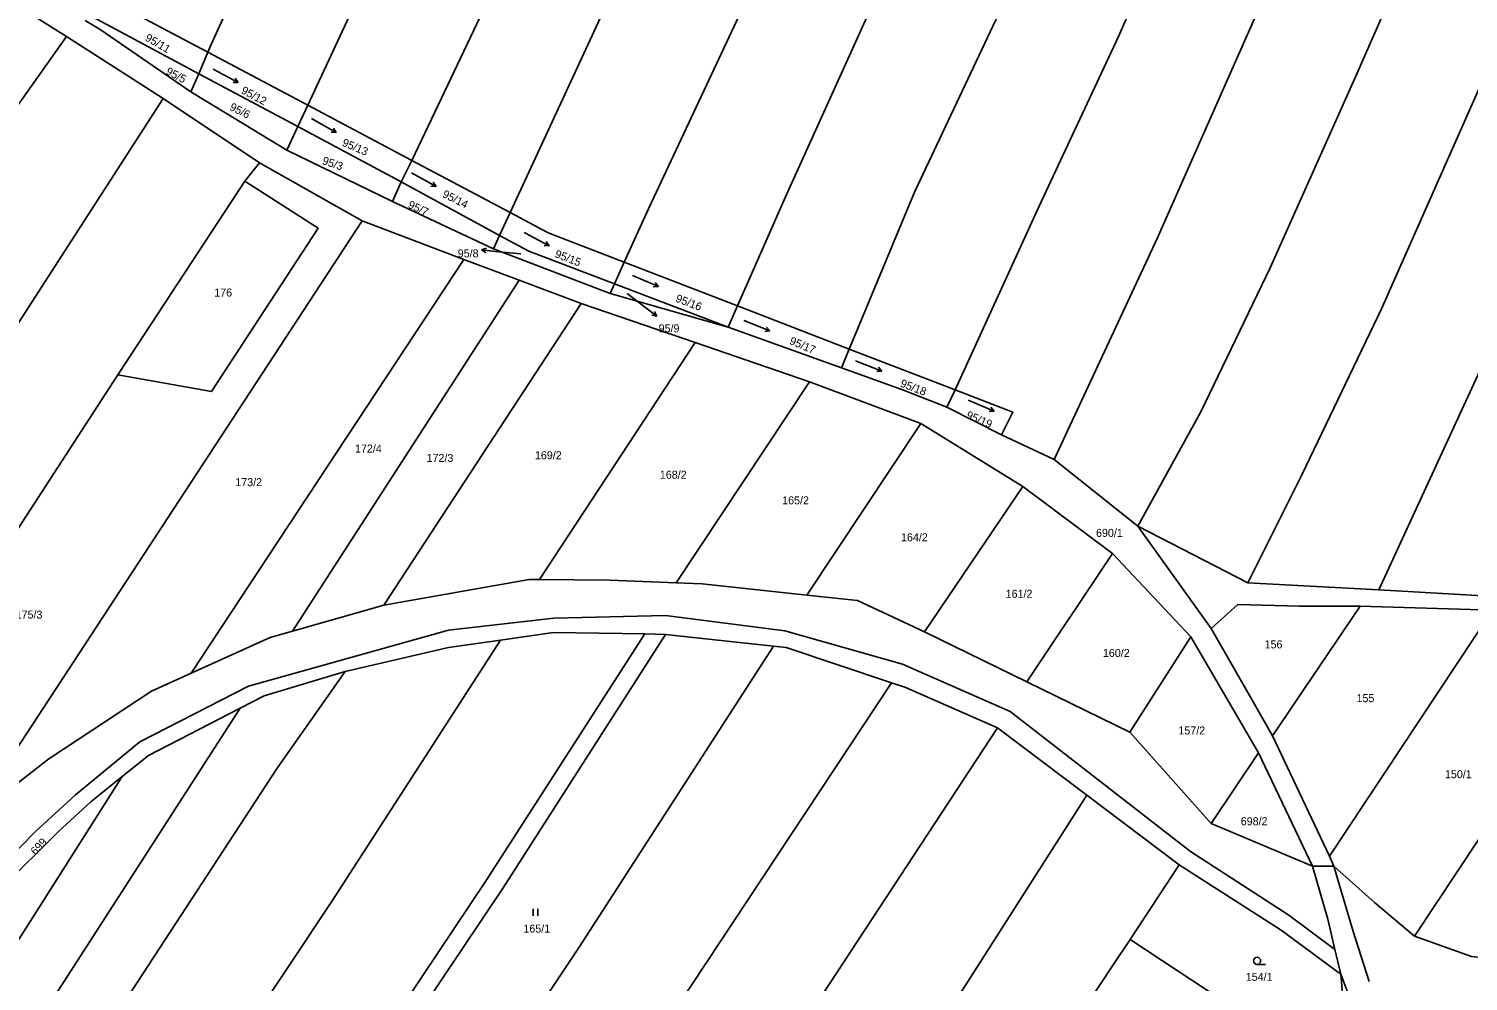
# Model space of a CAD drawing. Extents: x -747333 to -743907, y -1134120 to -1130051.
# Drawn here: x -746642.5 to -746336.6, y -1131625.6 to -1131423.1 of the extents above; entities that cross this region are included whole.
import ezdxf

# ---------------------------------------------------------------- set-up
doc = ezdxf.new("R2010")
doc.units = 0
for name, color, linetype in [('Hranice parcel', 7, 'Continuous'), ('Parcelní čísla', 7, 'Continuous'), ('Pop  PČ popisy', 7, 'Continuous'), ('Značky kultur', 7, 'Continuous')]:
    doc.layers.add(name, color=color, linetype=linetype)

msp = doc.modelspace()

# ---------------------------------------------------------------- linework, layer by layer
at = {"layer": 'Hranice parcel'}
for p, q in [((-746634.47, -1131424.8), (-746656.6, -1131410.85)), ((-746604.44, -1131428.12), (-746628.09, -1131415.58)), ((-746606.35, -1131432.7), (-746629.9, -1131420.11)), ((-746613.96, -1131437.96), (-746634.47, -1131424.8)), ((-746606.35, -1131432.7), (-746604.44, -1131428.12)), ((-746583.2, -1131439.38), (-746604.44, -1131428.12)), ((-746608.05, -1131436.52), (-746606.35, -1131432.7)), ((-746585.32, -1131443.94), (-746606.35, -1131432.7)), ((-746593.49, -1131451.66), (-746613.96, -1131437.96)), ((-746608.05, -1131436.52), (-746587.65, -1131448.97)), ((-746585.32, -1131443.94), (-746583.2, -1131439.38)), ((-746561.09, -1131451.11), (-746583.2, -1131439.38)), ((-746585.32, -1131443.94), (-746587.65, -1131448.97)), ((-746563.37, -1131455.67), (-746585.32, -1131443.94)), ((-746587.65, -1131448.97), (-746565.25, -1131459.83)), ((-746593.49, -1131451.66), (-746596.57, -1131455.55)), ((-746571.68, -1131464), (-746593.49, -1131451.66)), ((-746563.37, -1131455.67), (-746561.09, -1131451.11)), ((-746540.23, -1131462.22), (-746561.09, -1131451.11)), ((-746596.57, -1131455.55), (-746623.57, -1131496.7)), ((-746565.25, -1131459.83), (-746563.37, -1131455.67)), ((-746542.47, -1131467.06), (-746563.37, -1131455.67)), ((-746565.25, -1131459.83), (-746543.78, -1131469.9)), ((-746542.47, -1131467.06), (-746540.23, -1131462.22)), ((-746571.68, -1131464), (-746656.95, -1131594.27)), ((-746550.07, -1131472.15), (-746571.68, -1131464)), ((-746543.78, -1131469.9), (-746542.47, -1131467.06)), ((-746550.07, -1131472.15), (-746607.99, -1131560.1)), ((-746538.33, -1131476.58), (-746550.07, -1131472.15)), ((-746543.78, -1131469.9), (-746518.97, -1131479.42)), ((-746518.04, -1131477.36), (-746515.96, -1131472.78)), ((-746491.92, -1131482.06), (-746515.96, -1131472.78)), ((-746538.33, -1131476.58), (-746586.48, -1131551.19)), ((-746525.15, -1131481.55), (-746538.33, -1131476.58)), ((-746518.97, -1131479.42), (-746518.04, -1131477.36)), ((-746493.89, -1131486.54), (-746518.04, -1131477.36)), ((-746518.97, -1131479.42), (-746493.89, -1131486.54)), ((-746525.15, -1131481.55), (-746567.04, -1131545.66)), ((-746500.92, -1131489.85), (-746525.15, -1131481.55)), ((-746493.89, -1131486.54), (-746491.92, -1131482.06)), ((-746468.18, -1131491.22), (-746491.92, -1131482.06)), ((-746493.89, -1131486.54), (-746469.83, -1131495.19)), ((-746500.92, -1131489.85), (-746533.99, -1131540.23)), ((-746476.59, -1131498.19), (-746500.92, -1131489.85)), ((-746469.83, -1131495.19), (-746468.18, -1131491.22)), ((-746445.67, -1131499.91), (-746468.18, -1131491.22)), ((-746476.59, -1131498.19), (-746504.91, -1131540.89)), ((-746452.98, -1131507.05), (-746476.59, -1131498.19)), ((-746447.42, -1131503.6), (-746445.67, -1131499.91)), ((-746447.42, -1131503.6), (-746435.81, -1131509.47)), ((-746452.98, -1131507.05), (-746477.2, -1131543.56)), ((-746431.27, -1131520.46), (-746452.98, -1131507.05)), ((-746435.81, -1131509.47), (-746424.65, -1131514.71)), ((-746424.65, -1131514.71), (-746406.87, -1131528.87)), ((-746431.27, -1131520.46), (-746452.15, -1131551.35)), ((-746412.23, -1131534.7), (-746431.27, -1131520.46)), ((-746391.27, -1131550.61), (-746406.87, -1131528.87)), ((-746406.87, -1131528.87), (-746383.44, -1131540.92)), ((-746412.23, -1131534.7), (-746430.43, -1131561.92)), ((-746395.6, -1131552.41), (-746412.23, -1131534.7)), ((-746383.44, -1131540.92), (-746355.61, -1131542.43)), ((-746355.61, -1131542.43), (-746328.65, -1131543.97)), ((-746586.48, -1131551.19), (-746567.04, -1131545.66)), ((-746359.57, -1131545.85), (-746378.21, -1131573.45)), ((-746331.46, -1131546.72), (-746366.12, -1131598.98)), ((-746331.46, -1131546.72), (-746359.57, -1131545.85)), ((-746452.15, -1131551.35), (-746430.43, -1131561.92)), ((-746507.22, -1131551.86), (-746511.63, -1131551.78)), ((-746507.22, -1131551.86), (-746484.27, -1131554.35)), ((-746395.6, -1131552.41), (-746408.57, -1131572.64)), ((-746381.23, -1131577.03), (-746395.6, -1131552.41)), ((-746348.04, -1131615.98), (-746306.49, -1131553.28)), ((-746430.43, -1131561.92), (-746408.57, -1131572.64)), ((-746436.69, -1131571.7), (-746417.71, -1131586.04)), ((-746408.57, -1131572.64), (-746391.24, -1131592.08)), ((-746378.21, -1131573.45), (-746366.12, -1131598.98)), ((-746391.24, -1131592.08), (-746381.23, -1131577.03)), ((-746381.23, -1131577.03), (-746369.7, -1131601.11)), ((-746417.71, -1131586.04), (-746398.08, -1131600.88)), ((-746369.7, -1131601.11), (-746391.24, -1131592.08)), ((-746366.12, -1131598.98), (-746365.22, -1131601.11)), ((-746408.5, -1131616.68), (-746398.08, -1131600.88)), ((-746369.7, -1131601.11), (-746365.22, -1131601.11)), ((-746363.69, -1131624.1), (-746364.99, -1131618.82))]:
    msp.add_line(p, q, dxfattribs=at)
for points in [[(-746604.44, -1131428.12), (-746603.76, -1131426.5), (-746586.35, -1131388.11), (-746557.1, -1131325.3), (-746520.06, -1131246.03), (-746509.39, -1131224.25)], [(-746583.2, -1131439.38), (-746565.74, -1131401.78), (-746554.47, -1131378.66), (-746534.21, -1131333.41), (-746485.62, -1131231.14)], [(-746561.09, -1131451.11), (-746539.63, -1131405.92), (-746521.08, -1131363.53), (-746500.25, -1131318.99), (-746484.41, -1131286.87), (-746462.73, -1131237.74)], [(-746540.23, -1131462.22), (-746501.81, -1131379.22), (-746456.29, -1131281.73), (-746440.44, -1131244.89)], [(-746515.96, -1131472.78), (-746510.81, -1131461.44), (-746475.56, -1131386.07), (-746446.52, -1131320.69), (-746416.1, -1131252.46)], [(-746491.92, -1131482.06), (-746481.7, -1131458.87), (-746450.45, -1131389.79), (-746407.71, -1131295.56), (-746391.9, -1131259.94)], [(-746468.18, -1131491.22), (-746454.3, -1131457.87), (-746427.47, -1131400.92), (-746377.88, -1131289.13), (-746368.48, -1131267.37)], [(-746445.67, -1131499.91), (-746427.9, -1131461.01), (-746410.92, -1131424.76), (-746393.65, -1131385.36), (-746360.75, -1131310.12), (-746345.03, -1131274.96)], [(-746424.65, -1131514.71), (-746402.7, -1131467.7), (-746372.16, -1131398.47), (-746333.78, -1131310.4), (-746320.41, -1131282.95)], [(-746406.87, -1131528.87), (-746393.43, -1131504.53), (-746378.73, -1131473.98), (-746360.32, -1131432.73), (-746327.22, -1131357.37), (-746296.56, -1131290.28)], [(-746383.44, -1131540.92), (-746372.02, -1131517.94), (-746355.04, -1131482.69), (-746333.35, -1131433.58), (-746288.12, -1131328.39), (-746273.9, -1131297.53)], [(-746355.61, -1131542.43), (-746324.93, -1131475.84), (-746303.11, -1131426.75), (-746270.15, -1131349.38), (-746250.49, -1131305.53)], [(-746630.51, -1131421.39), (-746627.36, -1131423.33), (-746608.05, -1131436.52)], [(-746634.47, -1131424.8), (-746647.15, -1131442.71), (-746707, -1131534.29), (-746764.83, -1131622.3), (-746823.85, -1131714.89)], [(-746784.84, -1131701.9), (-746725.12, -1131609.01), (-746691.43, -1131558.02), (-746613.96, -1131437.96)], [(-746596.57, -1131455.55), (-746581, -1131465.55), (-746603.71, -1131500.27), (-746623.57, -1131496.7)], [(-746515.96, -1131472.78), (-746532.12, -1131466.54), (-746540.23, -1131462.22)], [(-746518.04, -1131477.36), (-746536.28, -1131470.43), (-746542.47, -1131467.06)], [(-746469.83, -1131495.19), (-746456.6, -1131499.95), (-746447.42, -1131503.6)], [(-746623.57, -1131496.7), (-746686.57, -1131593.72), (-746741.92, -1131680.58)], [(-746435.81, -1131509.47), (-746433.39, -1131504.65), (-746445.67, -1131499.91)], [(-746567.04, -1131545.66), (-746536.15, -1131540.21), (-746533.99, -1131540.23)], [(-746533.99, -1131540.23), (-746519.08, -1131540.36), (-746504.91, -1131540.89)], [(-746504.91, -1131540.89), (-746499.43, -1131541.1), (-746477.2, -1131543.56)], [(-746477.2, -1131543.56), (-746466.43, -1131544.63), (-746452.15, -1131551.35)], [(-746359.57, -1131545.85), (-746372.46, -1131545.89), (-746385.61, -1131545.48), (-746391.27, -1131550.61)], [(-746364.99, -1131618.82), (-746374.76, -1131611.53), (-746395.68, -1131598.02), (-746433.97, -1131568.23), (-746456.84, -1131558.16), (-746481.84, -1131551.09), (-746507.19, -1131547.87), (-746530.93, -1131548.41), (-746553.33, -1131550.96), (-746595.82, -1131562.87), (-746618.92, -1131574.71), (-746632.57, -1131585.95), (-746641.16, -1131593.8), (-746662.1, -1131615.23), (-746706.68, -1131661.84), (-746734.45, -1131685.19), (-746763.22, -1131703.17), (-746791.81, -1131716.66), (-746820.51, -1131725.51), (-746870.19, -1131733.65)], [(-746607.99, -1131560.1), (-746591.18, -1131552.52), (-746586.48, -1131551.19)], [(-746542.27, -1131553.07), (-746530.98, -1131551.43), (-746511.63, -1131551.78)], [(-746391.27, -1131550.61), (-746382.35, -1131566.17), (-746378.21, -1131573.45)], [(-746542.27, -1131553.07), (-746577.87, -1131608.3), (-746669.36, -1131745.76)], [(-746511.63, -1131551.78), (-746545.3, -1131604.15), (-746576.72, -1131651.31), (-746648.61, -1131760.36)], [(-746573.28, -1131689.92), (-746590.37, -1131678.32), (-746541.73, -1131605.72), (-746507.22, -1131551.86)], [(-746575.3, -1131559.78), (-746553.3, -1131554.68), (-746542.27, -1131553.07)], [(-746484.27, -1131554.35), (-746525.57, -1131618.34), (-746573.28, -1131689.92)], [(-746484.27, -1131554.35), (-746481.53, -1131554.65), (-746459.19, -1131562.15)], [(-746575.3, -1131559.78), (-746589.72, -1131580.27), (-746695.71, -1131742.45)], [(-746656.95, -1131594.27), (-746653.11, -1131589.86), (-746638.22, -1131578.32), (-746616.46, -1131563.92), (-746607.99, -1131560.1)], [(-746597.56, -1131567.52), (-746592.52, -1131564.91), (-746575.3, -1131559.78)], [(-746459.19, -1131562.15), (-746510.85, -1131640.22), (-746569.14, -1131726.93), (-746604.57, -1131782.51)], [(-746459.19, -1131562.15), (-746456.35, -1131563.1), (-746436.69, -1131571.7)], [(-746597.56, -1131567.52), (-746664.87, -1131671.92), (-746731.85, -1131775.88)], [(-746622.67, -1131582.09), (-746617.08, -1131577.63), (-746597.56, -1131567.52)], [(-746436.69, -1131571.7), (-746494.56, -1131659.94), (-746530.72, -1131713.92), (-746552.72, -1131746.93), (-746584.14, -1131795.8)], [(-746622.67, -1131582.09), (-746682.25, -1131675.86), (-746741.7, -1131769.31)], [(-746696.06, -1131655.22), (-746660.61, -1131618.22), (-746648.27, -1131605.81), (-746636.2, -1131593.74), (-746629.35, -1131587.43), (-746622.67, -1131582.09)], [(-746417.71, -1131586.04), (-746453.14, -1131641.65), (-746533.7, -1131761.53), (-746550, -1131786.81), (-746585.55, -1131841.66)], [(-746398.08, -1131600.88), (-746376.39, -1131614.72), (-746366.59, -1131621.96), (-746363.69, -1131624.1)], [(-746369.7, -1131601.11), (-746366.45, -1131612.42), (-746364.99, -1131618.82)], [(-746365.22, -1131601.11), (-746356.55, -1131608.86), (-746348.04, -1131615.98)], [(-746365.22, -1131601.11), (-746361.08, -1131615), (-746357.67, -1131625.64)], [(-746424.75, -1131641.3), (-746412.36, -1131622.52), (-746408.5, -1131616.68)], [(-746408.5, -1131616.68), (-746368.33, -1131643.18), (-746372.19, -1131649.02)], [(-746323.97, -1131621.69), (-746335.96, -1131620.33), (-746348.04, -1131615.98)], [(-746363.69, -1131624.1), (-746362.74, -1131635.52), (-746361.91, -1131641.27), (-746361.94, -1131643.54), (-746362.97, -1131645.86), (-746364.66, -1131647.42), (-746366.95, -1131648.25), (-746372.19, -1131649.02)], [(-746349.77, -1131699.8), (-746352.07, -1131674.11), (-746353.14, -1131664.9), (-746355.82, -1131651.29), (-746360.06, -1131633.75), (-746363.69, -1131624.1)]]:
    msp.add_lwpolyline(points, dxfattribs=at)
at = {"layer": 'Pop  PČ popisy'}
for p, q in [((-746546.285, -1131470.156), (-746545.236, -1131469.763)), ((-746543.3, -1131470.47), (-746546.285, -1131470.156)), ((-746546.285, -1131470.156), (-746545.341, -1131470.759)), ((-746537.97, -1131471), (-746543.3, -1131470.47)), ((-746515.35, -1131479.44), (-746511.41, -1131482.43)), ((-746511.41, -1131482.43), (-746509.013, -1131484.236)), ((-746509.013, -1131484.236), (-746510.114, -1131484.033)), ((-746509.013, -1131484.236), (-746509.512, -1131483.233))]:
    msp.add_line(p, q, dxfattribs=at)
at = {"layer": 'Značky kultur'}
for p, q in [((-746603.298, -1131431.737), (-746598, -1131434.554)), ((-746598, -1131434.554), (-746599.098, -1131434.538)), ((-746598, -1131434.554), (-746598.627, -1131433.653)), ((-746582.413, -1131442.251), (-746577.165, -1131445.16)), ((-746577.165, -1131445.16), (-746577.777, -1131444.248)), ((-746577.165, -1131445.16), (-746578.263, -1131445.125)), ((-746561.203, -1131453.731), (-746555.955, -1131456.64)), ((-746555.955, -1131456.64), (-746557.053, -1131456.605)), ((-746555.955, -1131456.64), (-746556.567, -1131455.728)), ((-746537.218, -1131466.437), (-746531.92, -1131469.254)), ((-746531.92, -1131469.254), (-746532.547, -1131468.353)), ((-746531.92, -1131469.254), (-746533.018, -1131469.238)), ((-746514.229, -1131475.592), (-746508.706, -1131477.937)), ((-746508.706, -1131477.937), (-746509.801, -1131478.017)), ((-746508.706, -1131477.937), (-746509.41, -1131477.093)), ((-746490.579, -1131485.131), (-746485.016, -1131487.378)), ((-746485.016, -1131487.378), (-746486.11, -1131487.477)), ((-746485.016, -1131487.378), (-746485.734, -1131486.547)), ((-746466.808, -1131493.739), (-746461.206, -1131495.889)), ((-746461.206, -1131495.889), (-746462.298, -1131496.007)), ((-746461.206, -1131495.889), (-746461.939, -1131495.071)), ((-746442.889, -1131502.072), (-746437.366, -1131504.417)), ((-746437.366, -1131504.417), (-746438.461, -1131504.497)), ((-746437.366, -1131504.417), (-746438.07, -1131503.573)), ((-746535.351, -1131611.7), (-746535.351, -1131610.2)), ((-746534.35, -1131611.7), (-746534.35, -1131610.2)), ((-746381.493, -1131622), (-746379.743, -1131622))]:
    msp.add_line(p, q, dxfattribs=at)
msp.add_circle((-746381.493, -1131621.25), 0.75, dxfattribs=at)

# ---------------------------------------------------------------- texts
at = {"layer": 'Parcelní čísla'}
for s, rotation, p in [('95/11', 330, (-746617.955, -1131425.536)), ('95/5', 332, (-746613.539, -1131432.7)), ('95/12', 332, (-746597.549, -1131436.77)), ('95/6', 333, (-746599.975, -1131440.297)), ('95/13', 337, (-746576.092, -1131447.952)), ('95/3', 341, (-746580.286, -1131451.853)), ('95/7', 335, (-746562.079, -1131461.13)), ('95/14', 333, (-746554.775, -1131458.817)), ('95/15', 339, (-746530.874, -1131471.653)), ('95/16', 339, (-746505.204, -1131481.103)), ('95/17', 337, (-746481.002, -1131490.082)), ('95/18', 339, (-746457.474, -1131499.153)), ('95/19', 337, (-746443.472, -1131505.852)), ('699', 47, (-746641.058, -1131598.899))]:
    msp.add_text(s, height=1.7, rotation=rotation, dxfattribs=at).set_placement(p)
for s, p in [('95/8', (-746551.352, -1131471.73)), ('176', (-746603.09, -1131480.06)), ('95/9', (-746508.67, -1131487.673)), ('172/4', (-746573.18, -1131513.21)), ('172/3', (-746557.98, -1131515.21)), ('169/2', (-746534.95, -1131514.64)), ('168/2', (-746508.41, -1131518.78)), ('173/2', (-746598.62, -1131520.36)), ('165/2', (-746482.42, -1131524.23)), ('690/1', (-746415.72, -1131531.14)), ('164/2', (-746457.16, -1131532.08)), ('161/2', (-746434.92, -1131544.09)), ('175/3', (-746645.3, -1131548.5)), ('156', (-746379.9, -1131554.84)), ('160/2', (-746414.26, -1131556.66)), ('155', (-746360.37, -1131566.27)), ('157/2', (-746398.22, -1131573.13)), ('150/1', (-746341.58, -1131582.43)), ('698/2', (-746384.973, -1131592.43)), ('165/1', (-746537.4, -1131615.25)), ('154/1', (-746383.903, -1131625.5))]:
    msp.add_text(s, height=1.7, dxfattribs=at).set_placement(p)

doc.saveas('drawing.dxf')
